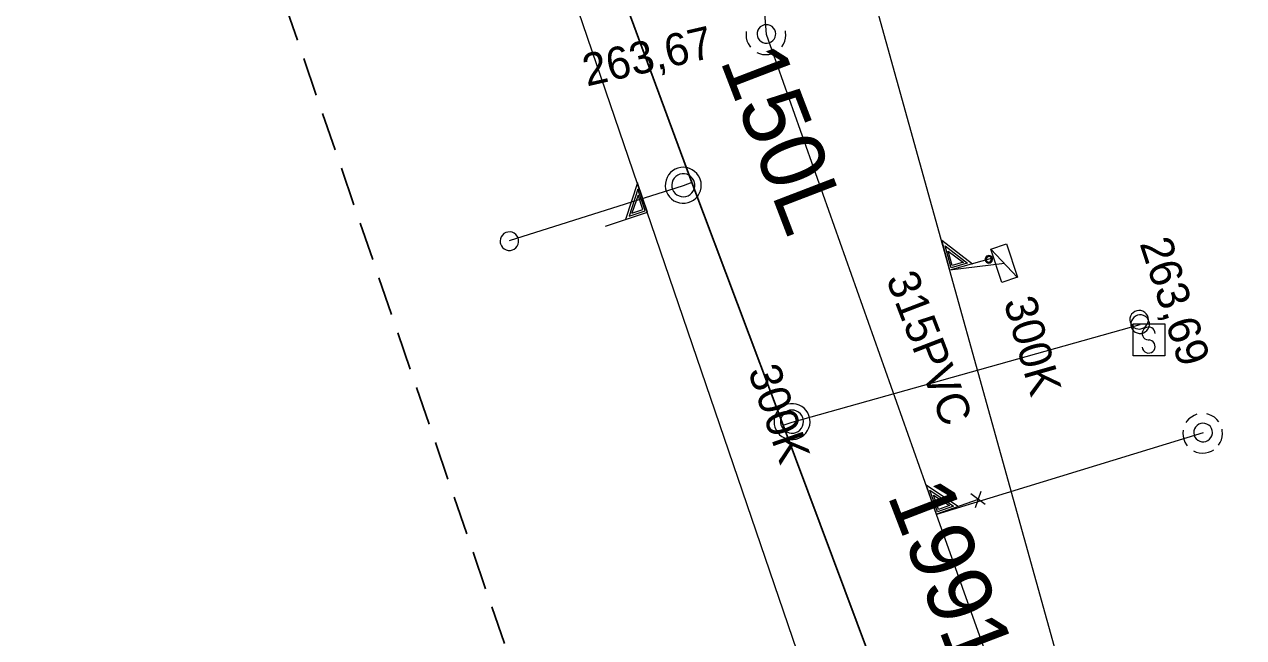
# Model space of a CAD drawing. Extents: x -732074 to -731966, y -1048695 to -1047982.
# Drawn here: x -732074 to -732043.73, y -1048447.33 to -1048432.1 of the extents above; entities that cross this region are included whole.
import ezdxf

# ---------------------------------------------------------------- set-up
doc = ezdxf.new("R2010")
doc.units = 0
doc.header["$LTSCALE"] = 0.32
doc.linetypes.add('MEDIUM_DASHED', pattern=[4.5, 3, -1.5])
doc.layers.add('1', color=7, linetype='Continuous')
for name, color, linetype, lineweight in [('18', 7, 'Continuous', 13), ('20', 7, 'Continuous', 13), ('49', 7, 'Continuous', 13), ('63', 7, 'MEDIUM_DASHED', 25), ('8', 7, 'Continuous', 13)]:
    doc.layers.add(name, color=color, linetype=linetype, lineweight=lineweight)

msp = doc.modelspace()

# ---------------------------------------------------------------- linework, layer by layer
at = {"layer": '18'}
for p, q in [((-732050.009, -1048437.686), (-732049.342, -1048438.386)), ((-732050.152, -1048444.031), (-732050.506, -1048443.763)), ((-732050.253, -1048443.708), (-732050.395, -1048444.114))]:
    msp.add_line(p, q, dxfattribs=at)
for points in [[(-732056.077, -1048432.279), (-732056.083, -1048432.356), (-732056.078, -1048432.433), (-732056.061, -1048432.508), (-732056.032, -1048432.579), (-732055.992, -1048432.645), (-732055.976, -1048432.667)], [(-732055.196, -1048432.656), (-732055.155, -1048432.591), (-732055.124, -1048432.521), (-732055.105, -1048432.446), (-732055.097, -1048432.37), (-732055.102, -1048432.293), (-732055.108, -1048432.258)], [(-732055.819, -1048432.796), (-732055.749, -1048432.827), (-732055.674, -1048432.846), (-732055.598, -1048432.853), (-732055.521, -1048432.848), (-732055.446, -1048432.831), (-732055.374, -1048432.803), (-732055.314, -1048432.768)], [(-732059.568, -1048437.117), (-732058.53, -1048436.763), (-732058.779, -1048436.033), (-732059.077, -1048436.95)], [(-732058.982, -1048436.863), (-732058.589, -1048436.729), (-732058.771, -1048436.194), (-732058.983, -1048436.864)], [(-732058.918, -1048436.792), (-732058.643, -1048436.698), (-732058.762, -1048436.346), (-732058.918, -1048436.793)], [(-732049.966, -1048437.912), (-732051.021, -1048438.205), (-732051.227, -1048437.463), (-732050.464, -1048438.05)], [(-732050.591, -1048438.034), (-732050.992, -1048438.145), (-732051.143, -1048437.6), (-732050.59, -1048438.034)], [(-732050.685, -1048438.011), (-732050.966, -1048438.089), (-732051.066, -1048437.731), (-732050.684, -1048438.012)], [(-732044.892, -1048441.787), (-732044.963, -1048441.815), (-732045.029, -1048441.854), (-732045.09, -1048441.902), (-732045.141, -1048441.959), (-732045.164, -1048441.993)], [(-732044.35, -1048441.97), (-732044.401, -1048441.912), (-732044.458, -1048441.862), (-732044.524, -1048441.821), (-732044.595, -1048441.792), (-732044.644, -1048441.778)], [(-732045.237, -1048442.179), (-732045.242, -1048442.256), (-732045.237, -1048442.333), (-732045.22, -1048442.408), (-732045.191, -1048442.479), (-732045.151, -1048442.545), (-732045.136, -1048442.567)], [(-732044.355, -1048442.556), (-732044.315, -1048442.491), (-732044.284, -1048442.421), (-732044.264, -1048442.346), (-732044.257, -1048442.27), (-732044.262, -1048442.193), (-732044.267, -1048442.158)], [(-732044.978, -1048442.696), (-732044.909, -1048442.727), (-732044.833, -1048442.746), (-732044.757, -1048442.753), (-732044.681, -1048442.748), (-732044.605, -1048442.731), (-732044.534, -1048442.703), (-732044.473, -1048442.668)], [(-732050.322, -1048443.902), (-732051.354, -1048444.268), (-732051.611, -1048443.543), (-732050.809, -1048444.075)], [(-732050.938, -1048444.068), (-732051.329, -1048444.206), (-732051.518, -1048443.673), (-732050.936, -1048444.067)], [(-732051.032, -1048444.051), (-732051.307, -1048444.149), (-732051.431, -1048443.798), (-732051.031, -1048444.052)]]:
    msp.add_lwpolyline(points, dxfattribs=at)
for points in [[(-732055.348, -1048432.339), (-732055.354, -1048432.287), (-732055.372, -1048432.237), (-732055.4, -1048432.193), (-732055.438, -1048432.156), (-732055.483, -1048432.129), (-732055.533, -1048432.113), (-732055.585, -1048432.108), (-732055.637, -1048432.115), (-732055.686, -1048432.134), (-732055.73, -1048432.164), (-732055.765, -1048432.203), (-732055.791, -1048432.248), (-732055.806, -1048432.299), (-732055.809, -1048432.351), (-732055.801, -1048432.403), (-732055.78, -1048432.451), (-732055.75, -1048432.494), (-732055.71, -1048432.529), (-732055.664, -1048432.553), (-732055.613, -1048432.567), (-732055.561, -1048432.569), (-732055.509, -1048432.559), (-732055.461, -1048432.537), (-732055.419, -1048432.505), (-732055.386, -1048432.465), (-732055.362, -1048432.418), (-732055.35, -1048432.367)], [(-732049.619, -1048437.553), (-732049.343, -1048438.382), (-732049.734, -1048438.512), (-732050.01, -1048437.683)], [(-732050.082, -1048437.847), (-732050.112, -1048437.861), (-732050.135, -1048437.885), (-732050.148, -1048437.916), (-732050.15, -1048437.95), (-732050.14, -1048437.981), (-732050.119, -1048438.007), (-732050.09, -1048438.025), (-732050.057, -1048438.032), (-732050.025, -1048438.026), (-732049.996, -1048438.01), (-732049.974, -1048437.984), (-732049.963, -1048437.952), (-732049.964, -1048437.919), (-732049.976, -1048437.887), (-732049.999, -1048437.862), (-732050.028, -1048437.847), (-732050.062, -1048437.843)], [(-732050.075, -1048437.873), (-732050.101, -1048437.886), (-732050.119, -1048437.908), (-732050.124, -1048437.935), (-732050.12, -1048437.963), (-732050.104, -1048437.987), (-732050.079, -1048438.001), (-732050.051, -1048438.004), (-732050.025, -1048437.996), (-732050.004, -1048437.977), (-732049.992, -1048437.951), (-732049.992, -1048437.923), (-732050.003, -1048437.897), (-732050.025, -1048437.879), (-732050.051, -1048437.87)], [(-732044.507, -1048442.239), (-732044.514, -1048442.187), (-732044.531, -1048442.137), (-732044.559, -1048442.093), (-732044.598, -1048442.056), (-732044.642, -1048442.029), (-732044.693, -1048442.013), (-732044.745, -1048442.008), (-732044.796, -1048442.015), (-732044.845, -1048442.034), (-732044.889, -1048442.064), (-732044.924, -1048442.103), (-732044.951, -1048442.148), (-732044.965, -1048442.199), (-732044.968, -1048442.251), (-732044.96, -1048442.303), (-732044.94, -1048442.351), (-732044.909, -1048442.394), (-732044.87, -1048442.429), (-732044.823, -1048442.453), (-732044.772, -1048442.467), (-732044.72, -1048442.469), (-732044.669, -1048442.459), (-732044.62, -1048442.437), (-732044.578, -1048442.405), (-732044.546, -1048442.365), (-732044.522, -1048442.318), (-732044.509, -1048442.267)]]:
    msp.add_lwpolyline(points, close=True, dxfattribs=at)
at = {"layer": '20'}
for p, q in [((-732047.59, -1048450.57), (-732053.92, -1048427.8)), ((-732047.59, -1048450.57), (-732053.92, -1048427.8)), ((-732051.489, -1048457.41), (-732060.89, -1048429.86)), ((-732051.489, -1048457.41), (-732060.89, -1048429.86))]:
    msp.add_line(p, q, dxfattribs=at)
for points in [[(-732055.579, -1048432.35), (-732056.217, -1048424.068), (-732057.272, -1048410.408), (-732058.87, -1048389.67)], [(-732055.579, -1048432.35), (-732056.217, -1048424.068), (-732057.272, -1048410.408), (-732058.87, -1048389.67)], [(-732047.25, -1048455.84), (-732049.379, -1048449.833), (-732051.352, -1048444.273), (-732055.579, -1048432.35)], [(-732047.25, -1048455.84), (-732049.379, -1048449.833), (-732051.352, -1048444.273), (-732055.579, -1048432.35)]]:
    msp.add_lwpolyline(points, dxfattribs=at)
at = {"layer": '49'}
for p, q in [((-732049.67, -1048438.04), (-732051.026, -1048438.206)), ((-732049.67, -1048438.04), (-732051.026, -1048438.206)), ((-732044.739, -1048442.25), (-732051.352, -1048444.273)), ((-732044.739, -1048442.25), (-732051.352, -1048444.273))]:
    msp.add_line(p, q, dxfattribs=at)
at = {"layer": '63'}
msp.add_lwpolyline([(-732022.871, -1048561.909), (-732073.995, -1048412.717), (-732073.996, -1048412.715), (-732073.996, -1048412.713), (-732069.268, -1048320.574)], dxfattribs=at)
at = {"layer": '8'}
for p, q in [((-732057.64, -1048436.11), (-732061.963, -1048437.478)), ((-732057.43, -1048436.03), (-732057.64, -1048436.11)), ((-732054.94, -1048441.98), (-732046.3, -1048439.56)), ((-732055.16, -1048442.06), (-732054.94, -1048441.98))]:
    msp.add_line(p, q, dxfattribs=at)
at = {"layer": '8', "lineweight": 25}
msp.add_lwpolyline([(-732060.37, -1048418.12), (-732059.43, -1048430.6), (-732057.43, -1048436.03), (-732055.16, -1048442.06), (-732051.16, -1048452.78), (-732050.93, -1048453.401), (-732046.69, -1048464.651), (-732045.92, -1048466.511), (-732044.12, -1048470.56)], dxfattribs=at)
at = {"layer": '8'}
for points in [[(-732057.206, -1048435.995), (-732057.229, -1048435.925), (-732057.263, -1048435.86), (-732057.307, -1048435.802), (-732057.36, -1048435.752), (-732057.42, -1048435.71), (-732057.486, -1048435.679), (-732057.556, -1048435.66), (-732057.629, -1048435.651), (-732057.702, -1048435.655), (-732057.774, -1048435.672), (-732057.842, -1048435.699), (-732057.905, -1048435.738), (-732057.959, -1048435.784), (-732058.006, -1048435.841), (-732058.044, -1048435.904), (-732058.07, -1048435.972), (-732058.084, -1048436.045), (-732058.088, -1048436.117), (-732058.079, -1048436.19), (-732058.058, -1048436.26), (-732058.026, -1048436.326), (-732057.984, -1048436.385), (-732057.932, -1048436.438), (-732057.873, -1048436.48), (-732057.807, -1048436.513), (-732057.738, -1048436.535), (-732057.665, -1048436.545), (-732057.592, -1048436.543), (-732057.52, -1048436.529), (-732057.451, -1048436.503), (-732057.388, -1048436.467), (-732057.331, -1048436.42), (-732057.282, -1048436.365), (-732057.244, -1048436.304), (-732057.216, -1048436.236), (-732057.199, -1048436.165), (-732057.194, -1048436.092), (-732057.201, -1048436.019)], [(-732057.363, -1048436.032), (-732057.382, -1048435.977), (-732057.412, -1048435.927), (-732057.452, -1048435.884), (-732057.5, -1048435.85), (-732057.553, -1048435.825), (-732057.61, -1048435.813), (-732057.669, -1048435.813), (-732057.727, -1048435.825), (-732057.78, -1048435.848), (-732057.828, -1048435.882), (-732057.868, -1048435.924), (-732057.899, -1048435.974), (-732057.919, -1048436.029), (-732057.927, -1048436.087), (-732057.924, -1048436.145), (-732057.908, -1048436.202), (-732057.881, -1048436.254), (-732057.845, -1048436.3), (-732057.799, -1048436.336), (-732057.747, -1048436.364), (-732057.691, -1048436.38), (-732057.633, -1048436.384), (-732057.575, -1048436.377), (-732057.52, -1048436.357), (-732057.469, -1048436.328), (-732057.426, -1048436.288), (-732057.392, -1048436.24), (-732057.369, -1048436.187), (-732057.357, -1048436.129), (-732057.357, -1048436.071)], [(-732062.178, -1048437.556), (-732062.157, -1048437.604), (-732062.125, -1048437.646), (-732062.085, -1048437.68), (-732062.037, -1048437.704), (-732061.986, -1048437.716), (-732061.934, -1048437.716), (-732061.883, -1048437.705), (-732061.835, -1048437.682), (-732061.794, -1048437.65), (-732061.761, -1048437.608), (-732061.74, -1048437.56), (-732061.729, -1048437.509), (-732061.73, -1048437.456), (-732061.743, -1048437.405), (-732061.766, -1048437.358), (-732061.801, -1048437.319), (-732061.842, -1048437.287), (-732061.891, -1048437.266), (-732061.942, -1048437.257), (-732061.995, -1048437.259), (-732062.045, -1048437.273), (-732062.092, -1048437.298), (-732062.131, -1048437.334), (-732062.161, -1048437.377), (-732062.18, -1048437.425), (-732062.189, -1048437.477), (-732062.185, -1048437.529)], [(-732046.096, -1048439.438), (-732046.102, -1048439.386), (-732046.12, -1048439.336), (-732046.148, -1048439.292), (-732046.186, -1048439.255), (-732046.231, -1048439.228), (-732046.281, -1048439.212), (-732046.333, -1048439.207), (-732046.385, -1048439.214), (-732046.434, -1048439.233), (-732046.478, -1048439.263), (-732046.513, -1048439.302), (-732046.539, -1048439.347), (-732046.554, -1048439.398), (-732046.557, -1048439.45), (-732046.549, -1048439.502), (-732046.528, -1048439.55), (-732046.498, -1048439.593), (-732046.458, -1048439.628), (-732046.412, -1048439.652), (-732046.361, -1048439.666), (-732046.309, -1048439.668), (-732046.257, -1048439.658), (-732046.209, -1048439.636), (-732046.167, -1048439.604), (-732046.134, -1048439.564), (-732046.11, -1048439.517), (-732046.098, -1048439.466)], [(-732046.079, -1048439.486), (-732046.099, -1048439.438), (-732046.13, -1048439.394), (-732046.168, -1048439.359), (-732046.215, -1048439.334), (-732046.266, -1048439.32), (-732046.318, -1048439.318), (-732046.369, -1048439.328), (-732046.418, -1048439.348), (-732046.46, -1048439.38), (-732046.494, -1048439.421), (-732046.517, -1048439.468), (-732046.53, -1048439.518), (-732046.531, -1048439.571), (-732046.52, -1048439.622), (-732046.498, -1048439.67), (-732046.465, -1048439.71), (-732046.424, -1048439.744), (-732046.376, -1048439.767), (-732046.325, -1048439.777), (-732046.273, -1048439.777), (-732046.222, -1048439.765), (-732046.175, -1048439.741), (-732046.134, -1048439.707), (-732046.102, -1048439.665), (-732046.081, -1048439.618), (-732046.071, -1048439.566), (-732046.073, -1048439.514)], [(-732046.478, -1048439.537), (-732045.689, -1048439.537), (-732045.689, -1048440.337), (-732046.478, -1048440.337)], [(-732054.522, -1048441.816), (-732054.553, -1048441.749), (-732054.594, -1048441.689), (-732054.644, -1048441.636), (-732054.702, -1048441.592), (-732054.767, -1048441.557), (-732054.836, -1048441.534), (-732054.908, -1048441.523), (-732054.982, -1048441.523), (-732055.054, -1048441.536), (-732055.124, -1048441.56), (-732055.188, -1048441.595), (-732055.245, -1048441.641), (-732055.294, -1048441.693), (-732055.335, -1048441.755), (-732055.365, -1048441.822), (-732055.383, -1048441.893), (-732055.389, -1048441.966), (-732055.384, -1048442.039), (-732055.366, -1048442.11), (-732055.338, -1048442.177), (-732055.298, -1048442.239), (-732055.25, -1048442.293), (-732055.192, -1048442.34), (-732055.129, -1048442.375), (-732055.06, -1048442.4), (-732054.988, -1048442.413), (-732054.915, -1048442.415), (-732054.842, -1048442.405), (-732054.772, -1048442.383), (-732054.707, -1048442.349), (-732054.648, -1048442.306), (-732054.597, -1048442.253), (-732054.555, -1048442.193), (-732054.524, -1048442.127), (-732054.504, -1048442.056), (-732054.495, -1048441.984), (-732054.499, -1048441.911), (-732054.514, -1048441.84)], [(-732054.673, -1048441.871), (-732054.699, -1048441.818), (-732054.735, -1048441.772), (-732054.779, -1048441.734), (-732054.83, -1048441.706), (-732054.886, -1048441.687), (-732054.944, -1048441.682), (-732055.002, -1048441.688), (-732055.059, -1048441.707), (-732055.109, -1048441.736), (-732055.153, -1048441.775), (-732055.188, -1048441.822), (-732055.213, -1048441.874), (-732055.226, -1048441.931), (-732055.228, -1048441.991), (-732055.218, -1048442.048), (-732055.196, -1048442.102), (-732055.163, -1048442.151), (-732055.121, -1048442.192), (-732055.072, -1048442.223), (-732055.017, -1048442.245), (-732054.96, -1048442.254), (-732054.901, -1048442.252), (-732054.844, -1048442.237), (-732054.792, -1048442.212), (-732054.745, -1048442.177), (-732054.707, -1048442.132), (-732054.679, -1048442.08), (-732054.662, -1048442.025), (-732054.656, -1048441.967), (-732054.663, -1048441.909)]]:
    msp.add_lwpolyline(points, close=True, dxfattribs=at)
for points in [[(-732045.929, -1048439.783), (-732045.934, -1048439.74), (-732045.951, -1048439.699), (-732045.978, -1048439.665), (-732046.015, -1048439.639), (-732046.056, -1048439.624), (-732046.099, -1048439.621), (-732046.142, -1048439.629), (-732046.181, -1048439.649), (-732046.214, -1048439.678), (-732046.237, -1048439.716), (-732046.249, -1048439.758), (-732046.25, -1048439.801), (-732046.238, -1048439.844), (-732046.216, -1048439.881), (-732046.184, -1048439.912), (-732046.146, -1048439.932), (-732046.103, -1048439.941), (-732046.076, -1048439.941)], [(-732046.252, -1048440.12), (-732046.242, -1048440.163), (-732046.22, -1048440.202), (-732046.189, -1048440.233), (-732046.151, -1048440.254), (-732046.108, -1048440.265), (-732046.064, -1048440.263), (-732046.022, -1048440.25), (-732045.985, -1048440.226), (-732045.956, -1048440.193), (-732045.937, -1048440.153), (-732045.929, -1048440.11), (-732045.933, -1048440.066), (-732045.949, -1048440.025), (-732045.975, -1048439.99), (-732046.01, -1048439.963), (-732046.051, -1048439.946), (-732046.076, -1048439.941)]]:
    msp.add_lwpolyline(points, dxfattribs=at)

# ---------------------------------------------------------------- texts
at = {"layer": '1'}
for s, height, rotation, p in [('263,67', 0.8, 13, (-732060.036, -1048433.645)), ('150L', 1.6, 291, (-732056.738, -1048432.993)), ('263,69', 0.8, 288, (-732046.32, -1048437.542)), ('315PVC', 0.8, 291, (-732052.617, -1048438.417)), ('300K', 0.8, 286, (-732049.694, -1048438.987)), ('300K', 0.8, 289, (-732056.043, -1048440.711)), ('1991', 1.6, 291, (-732052.588, -1048443.793))]:
    msp.add_text(s, height=height, rotation=rotation, dxfattribs=at).set_placement(p)

doc.saveas('drawing.dxf')
